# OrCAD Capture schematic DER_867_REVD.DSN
size Custom; title: DER 867; rev: D
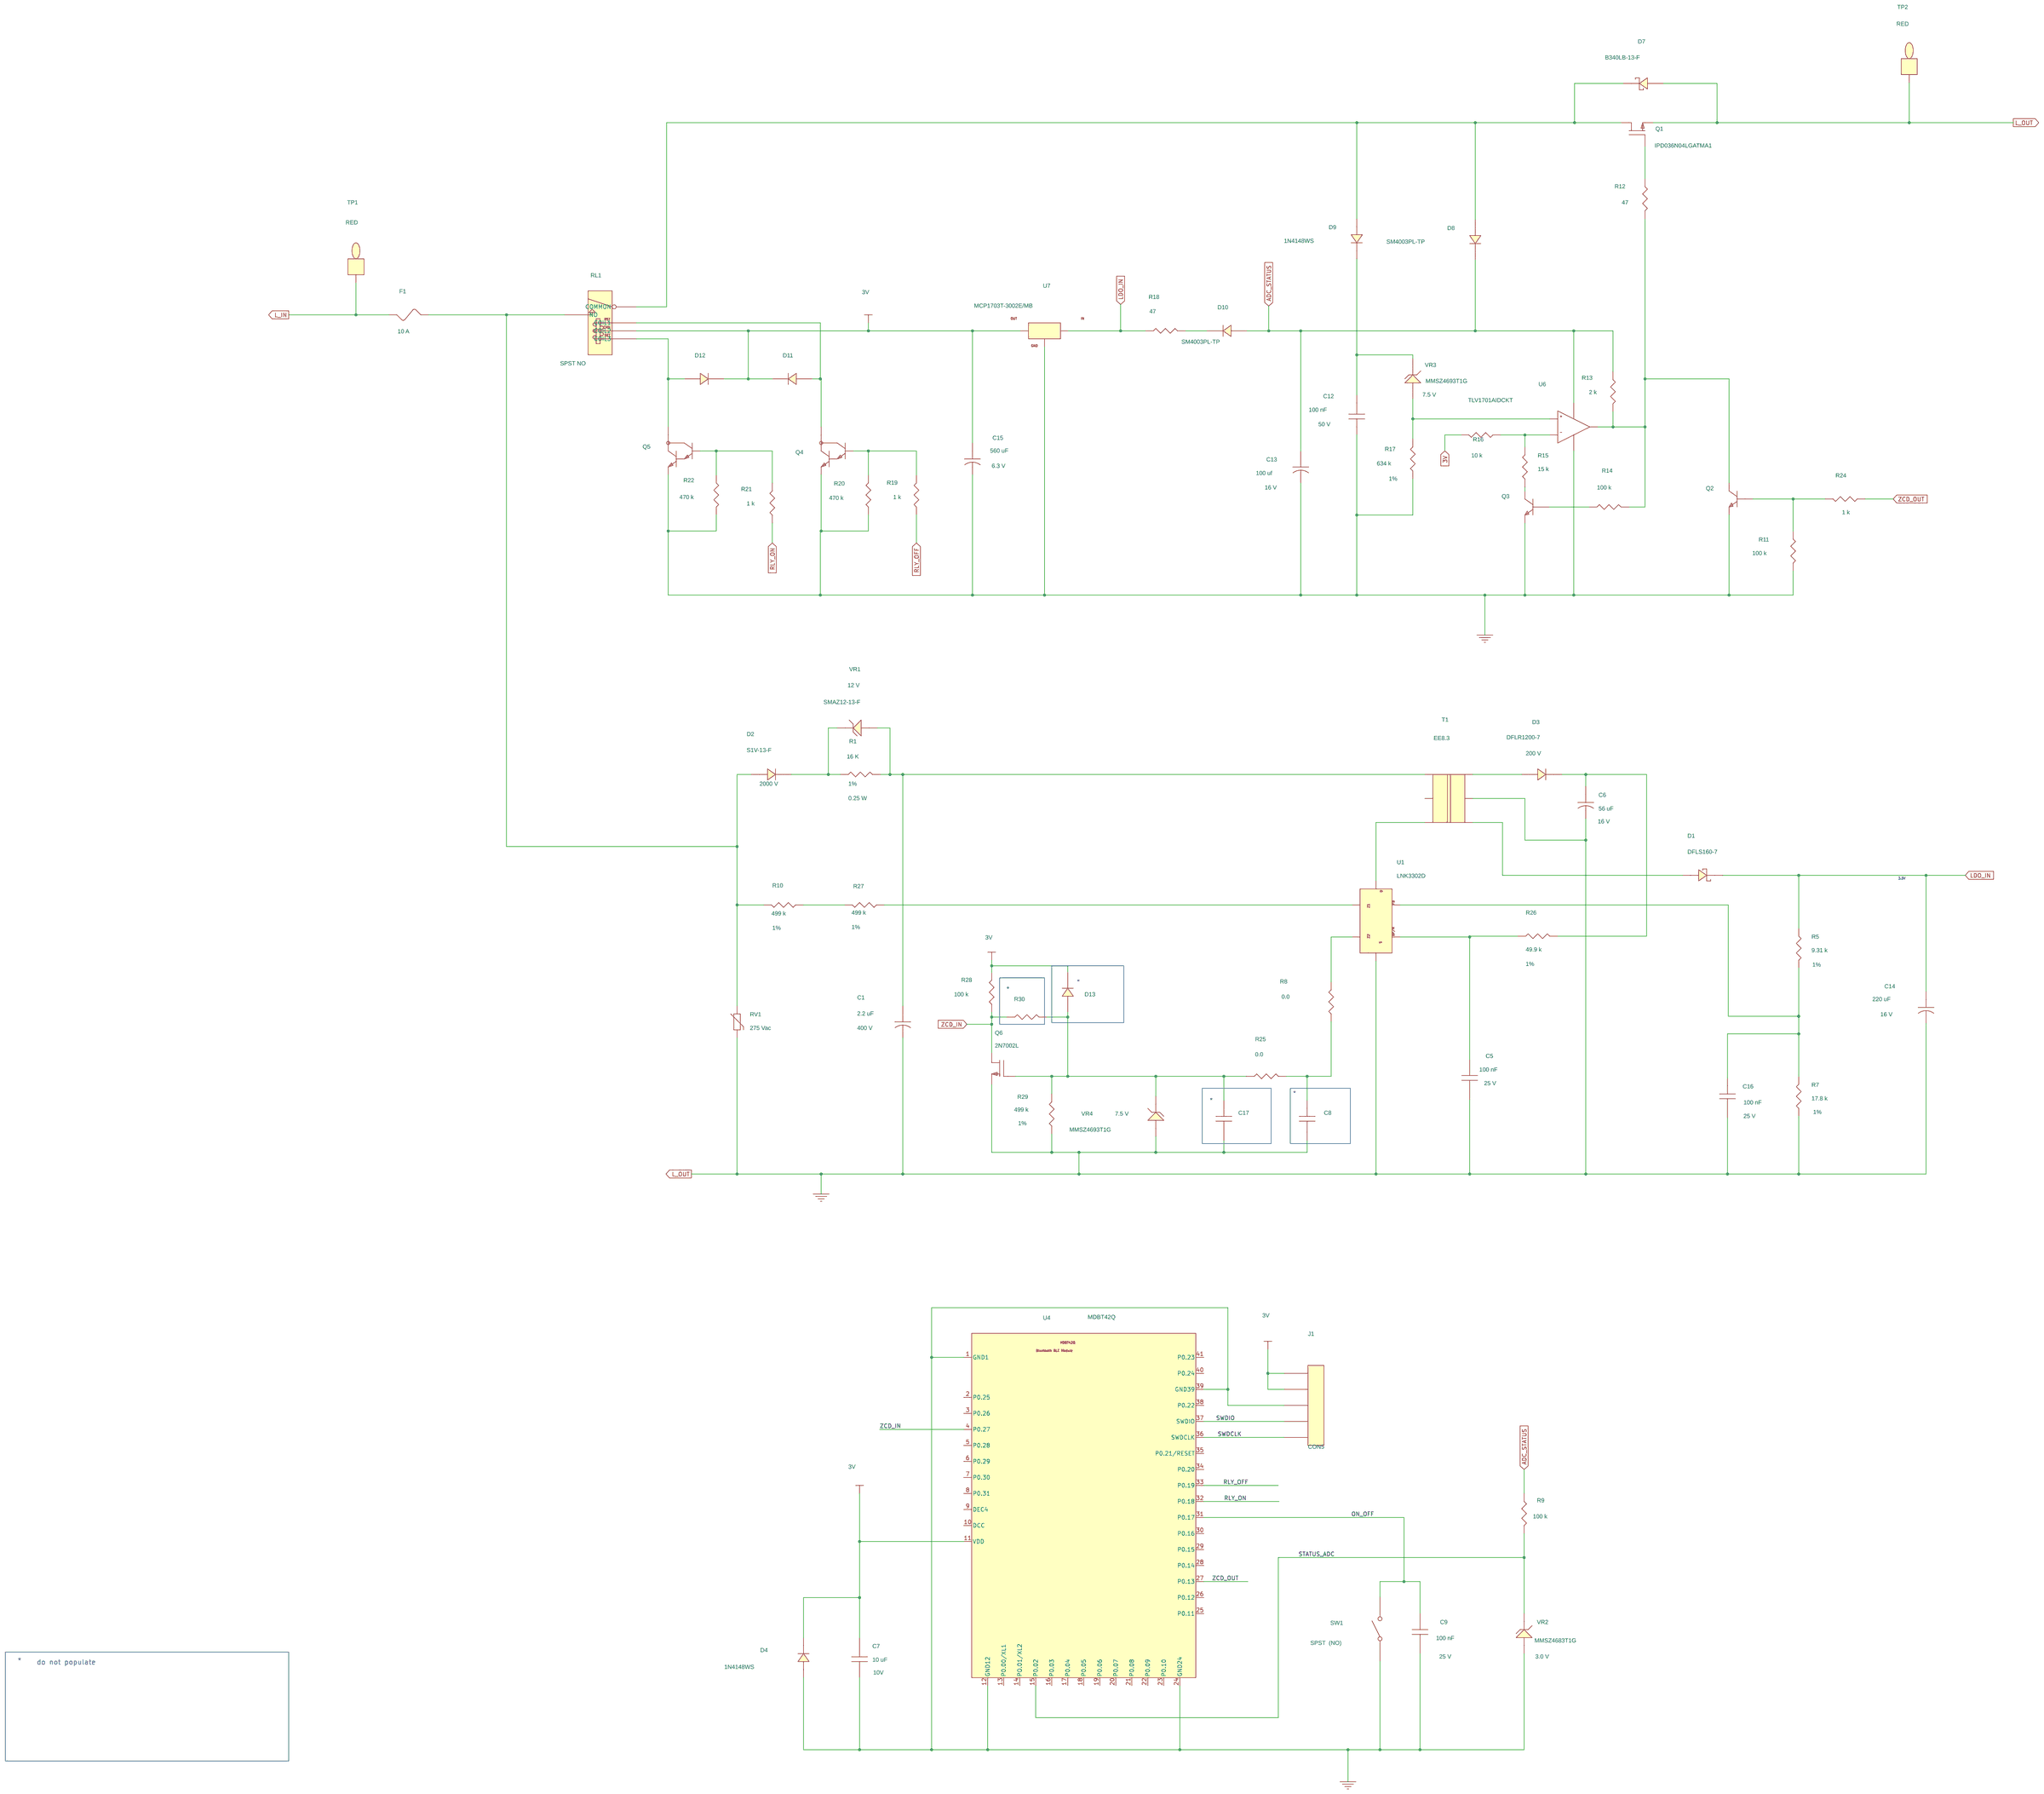
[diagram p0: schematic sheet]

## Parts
C1  2.2 uF  [pipolcap6p3x16p5d030]
C5  100 nF  [pismc0805]
C6  56 uF  [pipolcapclyd200ls80030]
C7  10 uF  [pismc0603]
C8  100 pF  [pismc0805]
C9  100 nF  [pismc0805]
C12  100 nF  [pismc0805]
C13  100 uf  [pipolcapclyd248ls098028]
C14  220 uF  [pipolcapclyd248ls098028]
C15  560 uF  [pipolcapcyld250ls100030]
C16  100 nF  [pismc0805]
C17  100 pF  [pismc0805]
D1  DFLS160-7  [pismddflr120012]
D2  S1V-13-F  [pi_sm_sod-123_12]
D3  DFLR1200-7  [pismddflr120012]
D4  1N4148WS  [pismdsod323]
D7  B340LB-13-F  [pismdo214aa12]
D8  SM4003PL-TP  [pi_sm_sod-123_12]
D9  1N4148WS  [pismdsod323]
D10  SM4003PL-TP  [pi_sm_sod-123_12]
D11  BAV16WS-7-F  [pismsod323]
D12  BAV16WS-7-F  [pismsod323]
D13  DNP  [pismdsod323]
F1  10 A  [pismFuse10p1x3p0]
J1  CON5  [PI_HDRF_1X5_Hirose]
Q1  IPD036N04LGATMA1  [pismddpak]
Q2  MMBT3904  [pismsot23123_1]
Q3  MMBT3904  [pismsot23123_1]
Q4  MMBT6427-7-F  [pismsot23123_1]
Q5  MMBT6427-7-F  [pismsot23123_1]
Q6  2N7002L  [pismsot23123_1]
R1  16 K  [pismr1206]
R5  9.31 k  [pismr0805]
R7  17.8 k  [pismr0805]
R8  0.0  [pismr0805]
R9  100 k  [pismr0603]
R10  499 k  [pismr0805]
R11  100 k  [pismr0603]
R12  47  [pismr0805]
R13  2 k  [pismr0603]
R14  100 k  [pismr0603]
R15  15 k  [pismr0603]
R16  10 k  [pismr0603]
R17  634 k  [pismr0603]
R18  47  [pismr0805]
R19  1 k  [pismr0603]
R20  470 k  [pismr0603]
R21  1 k  [pismr0603]
R22  470 k  [pismr0603]
R24  1 k  [pismr0603]
R25  0.0  [pismr0805]
R26  49.9 k  [pismr0805]
R27  499 k  [pismr0805]
R28  100 k  [pismr0805]
R29  499 k  [pismr0805]
R30  0  [pismr0805]
RL1  SPST NO  [pi_rly-panasonic_2Coil]
RV1  275 Vac  [pi_disc276x181_ls200x83d040]
SW1  SPST  (NO)  [pi_switch_spst_tl59]
T1  EE8.3  [pi_bobbin_ee8_3_v6p]
TP1  RED  [pitpkeystone125x125]
TP2  RED  [pitpkeystone125x125]
U1  LNK3302D  [pismso8_nop3]
U4  MDBT42Q  [pi_Mod_Raytac_MDBT42Q]
U6  TLV1701AIDCKT  [pismsc705]
U7  MCP1703T-3002E/MB  [pi_sm_sot89-3]
VR1  SMAZ12-13-F  [pismdo214ac12]
VR2  MMSZ4683T1G  [pi_sm_sod-123_12]
VR3  MMSZ4693T1G  [pi_sm_sod-123_12]
VR4  MMSZ4693T1G  [pi_sm_sod-123_12]

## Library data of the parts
C1 = CAP_POL: ALT_SYMBOLS: pipolcap6p3x16p5d030H; Disp_Voltage: 400 V; FPLIST: pipolcap6p3x16p5d030,pipolcap6p3x16p5d030H; Part Number: 20-01686-00; Voltage: 400 V
C5 C9 C16 = CAP_NP: Disp_Voltage: 25 V; Part Number: 20-08599-00; Voltage: 25 V
C6 = CAP_POL: Disp_Voltage: 16 V; Part Number: 20-00877-00; Voltage: 16 V
C7 = CAP_NP: Disp_Voltage: 10V; Part Number: 20-01014-00; ROOM: 3; Voltage: 10 V
C8 C17 = CAP_NP: Disp_Voltage: 100 V; Part Number: 20-00581-00; Voltage: 100 V
C12 = CAP_NP: Disp_Voltage: 50 V; Part Number: 20-00904-00; ROOM: 1; Voltage: 50 V
C13 = CAP_POL: ALT_SYMBOLS: pipolcapclyd248ls098028_h; Disp_Voltage: 16 V; FPLIST: pipolcapclyd248ls098028,pipolcapclyd248ls098028_h; Part Number: 20-09114-00; Voltage: 16V
C14 = CAP_POL: ALT_SYMBOLS: pipolcapclyd6p3x9mm_h; Disp_Voltage: 16 V; FPLIST: pipolcapclyd248ls098028,pipolcapclyd6p3x9mm_h; Part Number: 20-09088-00; Voltage: 16V
C15 = CAP_POL: Disp_Voltage: 6.3 V; Part Number: 23-00058-00; Voltage: 6.3 V
D1 = DIODE_SCHOTTKY: Part Number: 15-00880-00
D2 = DIODE: Disp_Voltage: 2000 V; Part Number: 15-01782-00
D3 = DIODE: Disp_Voltage: 200 V; Part Number: 15-01019-00
D4 D13 = DIODE: Part Number: 15-01163-00; ROOM: 2
D7 = DIODE_SCHOTTKY: Part Number: 15-00824-00; ROOM: 1
D8 D10 = DIODE: Part Number: 15-01052-00
D9 = DIODE: Part Number: 15-01163-00
D11 D12 = DIODE: Part Number: 15-00850-00; ROOM: 2
F1 = FUSE: Part Number: 40-00088-00
J1 = CON5: Part Number: 35-00428-00
Q1 = FET_N_GDS: ALT_SYMBOLS: pi_sm_d_pak_1; FPLIST: pismddpak,pi_sm_d_pak_1; Part Number: 50-00381-00; ROOM: 1
Q2 Q3 = NPN_BEC: Part Number: 55-00048-00; ROOM: 1
Q4 Q5 = NPN_DAR_BEC: Part Number: 55-00105-00; ROOM: 2
Q6 = FET_N_GSD: Part Number: 50-00364-00
R1 = R: ALT_SYMBOLS: pismr1206_1; Disp_Power: 0.25 W; Disp_Tol: 1%; FPLIST: pismr1206,pismr1206_1; Part Number: 05-06505-00
R5 = R: Disp_Tol: 1%; Part Number: 05-03307-00
R7 = R: Disp_Tol: 1%; Part Number: 05-00708-00
R8 = R: ALT_SYMBOLS: pismr0805_1; FPLIST: pismr0805,pismr0805_1; Part Number: 05-03159-00; Tol: 1%
R9 = R: Part Number: 05-01736-00; ROOM: 2
R10 R27 = R: Disp_Tol: 1%; Part Number: 05-00847-00; ROOM: 1
R11 R14 = R: Part Number: 05-01736-00; ROOM: 1
R12 R18 = R: Part Number: 05-01487-00; ROOM: 1
R13 = R: ALT_SYMBOLS: pismr0603_1; FPLIST: pismr0603,pismr0603_1; Part Number: 05-01695-00; ROOM: 1
R15 = R: Part Number: 05-01716-00; ROOM: 1
R16 = R: Part Number: 05-01712-00; ROOM: 1
R17 = R: Disp_Tol: 1%; Part Number: 05-01251-00; ROOM: 1
R19 R21 = R: Part Number: 05-01688-00; ROOM: 2
R20 R22 = R: Part Number: 05-01752-00; ROOM: 2
R24 = R: Part Number: 05-01688-00; ROOM: 1
R25 = R: ALT_SYMBOLS: pismr0805_1; FPLIST: pismr0805,pismr0805_1; Part Number: 05-03159-00
R26 = R: Disp_Tol: 1%; Part Number: 05-00751-00
R28 = R: Part Number: 05-01567-00
R29 = R: Disp_Tol: 1%; Part Number: 05-00847-00; Tol: 1%
R30 = R: Disp_Power: 0.25 W; Part Number: 05-06639-00
RL1 = RELAY_SPST_PANASONIC_DOUBLECOIL: Part Number: 66-00221-00; ROOM: 2
RV1 = VARISTOR: Part Number: 85-00040-00
SW1 = SW_SPST: Part Number: 66-00423-00
T1 = BEE8_3_6P: Part Number: 25-01086-00
TP1 TP2 = TESTPOINT: Part Number: 35-00043-00; ROOM: 2
U1 = LNK-TNZ: Part Number: 10-01234-00
U4 = Mod_Raytac_MDBT42Q: Part Number: 66-00255-00
U6 = TLV1701a: Part Number: 45-00687-00
U7 = LM78LXX_GIO: Part Number: 45-04519-00
VR1 = DIODE_ZENER: Disp_Voltage: 12 V; Part Number: 15-01776-00
VR2 = DIODE_ZENER: Disp_Voltage: 3.0 V; Part Number: 15-01576-00; ROOM: 3
VR3 VR4 = DIODE_ZENER: Disp_Voltage: 7.5 V; Part Number: 15-01578-00

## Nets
3V: C7.2 C15.1 D4.1 D11.1 D12.1 D13.1 J1.1 J1.2 R16.1 R28.1 RL1.7(COIL2) U4.11(VDD) U7.3(OUT)
ADC_STATUS: C13.1 D8.1 D10.2 R9.1 R13.2 U6.5
L_IN: F1.2 TP1.1
LDO_IN: C14.1 D1.1 R5.1 R18.2 U7.2(IN)
LINE_IN: C1.2 C5.2 C6.2 C7.1 C8.2 C9.2 C12.1 C13.2 C14.2 C15.2 C16.2 C17.2 D4.2 D7.2 J1.3 Q1.3(S) Q2.2(EMITTER) Q3.2(EMITTER) Q4.2(E) Q5.2(E) Q6.2(S) R7.1 R11.1 R17.2 R20.2 R22.2 R29.2 RV1.2 SW1.1 T1.5 TP2.1 U1.5 U4.1(GND1) U4.12(GND12) U4.24(GND24) U4.39(GND39) U6.2 U7.1(GND) VR2.2 VR4.2
ON_OFF: C9.1 SW1.2 U4.31(P0.17)
RLY_OFF: R19.2 U4.33(P0.19)
RLY_ON: R21.2 U4.32(P0.18)
STATUS_ADC: R9.2 U4.15(P0.02) VR2.1
SWDCLK: J1.5 U4.36(SWDCLK)
SWDIO: J1.4 U4.37(SWDIO)
ZCD_IN: Q6.3(D) R28.2 R30.1 U4.4(P0.27)
ZCD_OUT: R24.2 U4.27(P0.13)
N48269: D7.1 D8.2 D9.2 Q1.2(D) RL1.5(COMMON)
N49650: R17.1 U6.1 VR3.2
N51578: Q2.3(COLLECTOR) R12.2 R13.1 R14.1 U6.4
N257317: R15.2 R16.2 U6.3
N372848: D11.2 Q4.3(C) RL1.1(COIL1)
N372944: D12.2 Q5.3(C) RL1.6(COIL3)
N414217: Q1.1(G) R12.1
N423761: Q5.1(B) R21.1 R22.1
N460853: D10.1 R18.1
N471353: C12.2 D9.1 VR3.1
N477862: Q2.1(BASE) R11.2 R24.1
N518037: Q3.3(COLLECTOR) R15.1
N525361: Q4.1(B) R19.1 R20.1
N526799: Q3.1(BASE) R14.2
N595771: D2.2 F1.1 R10.1 RL1.3(NO) RV1.1
N598020: C1.1 R1.1 T1.1 VR1.2
N632777: R10.2 R27.1
N682309: R27.2 U1.1
N682418: T1.3 U1.4
N687847: D3.2 T1.6
N687859: C6.1 D3.1 R26.2
N687971: D1.2 T1.4
N688873: C16.1 R5.2 R7.2 U1.8
N704755: C5.1 R26.1 U1.7
N705901: C17.1 D13.2 Q6.1(G) R25.2 R29.1 R30.2 VR4.1
N724784: R8.1 U1.2
N755538: C8.1 R8.2 R25.1
N772684: D2.1 R1.2 VR1.1

Not connected (* = marked no-connect by the designer): T1 2; U1 6; U4 2(P0.25) 3(P0.26) 5(P0.28) 6(P0.29) 7(P0.30) 8(P0.31) 9(DEC4) 10(DCC) 13(P0.00/XL1) 14(PO.01/XL2) 16(P0.03) 17(P0.04) 18(P0.05) 19(P0.06) 20(P0.07) 21(P0.08) 22(P0.09) 23(P0.10) 25(P0.11) 26(P0.12) 28(P0.14) 29(P0.15) 30(P0.16) 34(P0.20) 35(P0.21/RESET) 38(P0.22) 40(P0.24) 41(P0.23)

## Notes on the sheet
- 3.5V
- *
- *
- *
- *
- *
- do not populate
